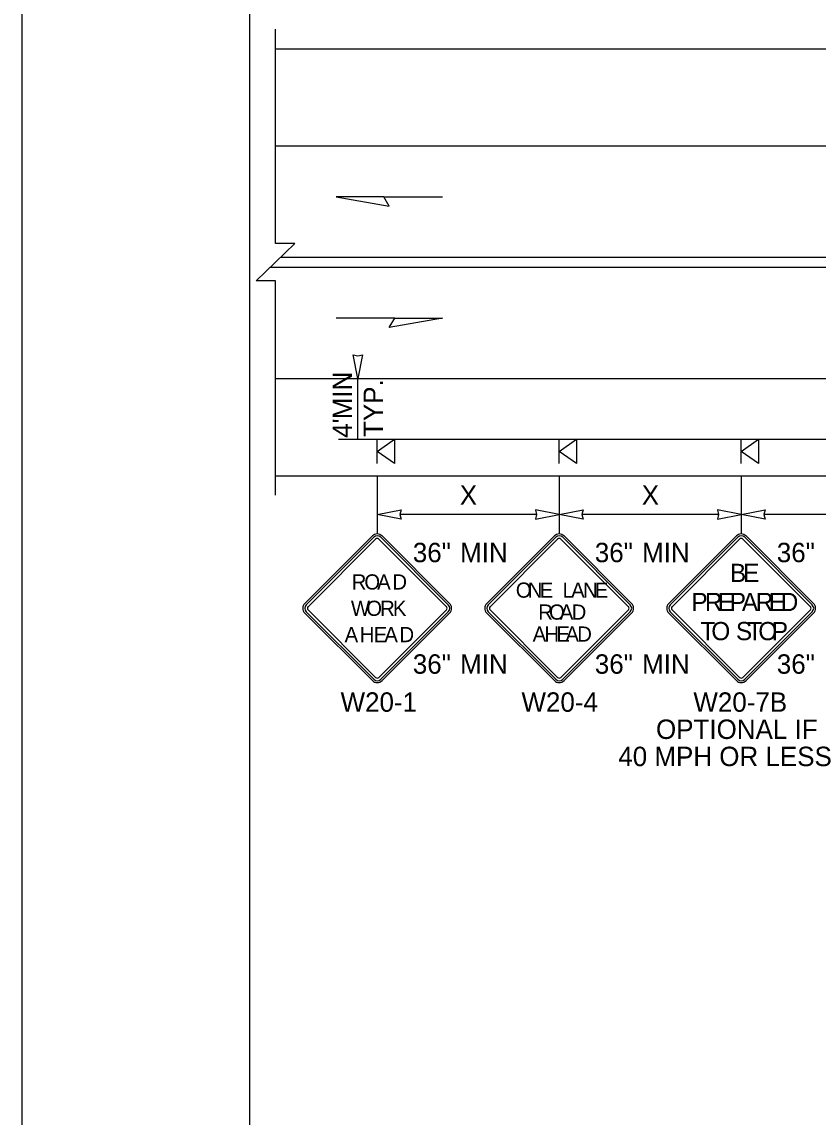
# Model space of a CAD drawing. Extents: x 99999.1 to 100095.7, y 99995 to 100010.7.
# Drawn here: x 99999.062 to 100002.344, y 100003.089 to 100007.603 of the extents above; entities that cross this region are included whole.
import ezdxf

# ---------------------------------------------------------------- set-up
doc = ezdxf.new("R2010")
doc.units = 0
for name, color, linetype in [('RD_ED_ShoulderPavedEdge', 7, 'Continuous'), ('RD_MK_LineDblYellowCenter', 7, 'Continuous'), ('RD_MK_LineEdgeWhite', 7, 'Continuous'), ('SH_GI_PlotLimits', 7, 'Continuous'), ('SH_GI_SheetBorder', 7, 'Continuous'), ('TR_SN_ConstructionSigns', 7, 'Continuous'), ('TR_WZ_PortableSignMountBlk-Org', 7, 'Continuous'), ('TR_WZ_WorkZoneDetails', 7, 'Continuous'), ('TR_WZ_WorkZoneTextCurrent', 7, 'Continuous')]:
    doc.layers.add(name, color=color, linetype=linetype)

msp = doc.modelspace()

# ---------------------------------------------------------------- linework, layer by layer
at = {"layer": 'RD_ED_ShoulderPavedEdge'}
for p, q in [((100000.1076, 100007.4923), (100015.6424, 100007.4923)), ((100000.1076, 100005.7323), (100015.6424, 100005.7323))]:
    msp.add_line(p, q, dxfattribs=at)
at = {"layer": 'RD_MK_LineDblYellowCenter'}
for p, q in [((100000.1282, 100006.6323), (100003.4767, 100006.6323)), ((100000.0869, 100006.5923), (100003.4767, 100006.5923))]:
    msp.add_line(p, q, dxfattribs=at)
at = {"layer": 'RD_MK_LineEdgeWhite'}
for p, q in [((100000.1076, 100007.0923), (100015.6424, 100007.0923)), ((100000.1076, 100006.1323), (100015.6424, 100006.1323))]:
    msp.add_line(p, q, dxfattribs=at)
at = {"layer": 'SH_GI_PlotLimits'}
msp.add_lwpolyline([(99999.0625, 99999.6875), (100016.0625, 99999.6875), (100016.0625, 100010.6875), (99999.0625, 100010.6875)], close=True, dxfattribs=at)
at = {"layer": 'SH_GI_SheetBorder'}
msp.add_line((100000, 100010.375), (100000, 100000), dxfattribs=at)
at = {"layer": 'TR_SN_ConstructionSigns'}
for p, q in [((100000.5068, 100005.4841), (100000.2283, 100005.2057)), ((100000.5123, 100005.4786), (100000.2339, 100005.2001)), ((100000.2416, 100005.1924), (100000.52, 100005.4708)), ((100000.5333, 100005.4708), (100000.8117, 100005.1924)), ((100000.8194, 100005.2001), (100000.541, 100005.4786)), ((100000.825, 100005.2057), (100000.5465, 100005.4841)), ((100001.2568, 100005.4841), (100000.9783, 100005.2057)), ((100001.2623, 100005.4786), (100000.9839, 100005.2001)), ((100000.9916, 100005.1924), (100001.27, 100005.4708)), ((100001.2833, 100005.4708), (100001.5617, 100005.1924)), ((100001.5694, 100005.2001), (100001.291, 100005.4786)), ((100001.575, 100005.2057), (100001.2965, 100005.4841)), ((100002.0068, 100005.4841), (100001.7283, 100005.2057)), ((100002.0123, 100005.4786), (100001.7339, 100005.2001)), ((100001.7416, 100005.1924), (100002.02, 100005.4708)), ((100002.0333, 100005.4708), (100002.3117, 100005.1924)), ((100002.3194, 100005.2001), (100002.041, 100005.4786)), ((100002.325, 100005.2057), (100002.0465, 100005.4841)), ((100000.52, 100004.9007), (100000.2416, 100005.1792)), ((100000.8117, 100005.1792), (100000.5333, 100004.9007)), ((100001.27, 100004.9007), (100000.9916, 100005.1792)), ((100001.5617, 100005.1792), (100001.2833, 100004.9007)), ((100002.02, 100004.9007), (100001.7416, 100005.1792)), ((100002.3117, 100005.1792), (100002.0333, 100004.9007)), ((100000.2283, 100005.1659), (100000.5068, 100004.8875)), ((100000.2339, 100005.1714), (100000.5123, 100004.893)), ((100000.541, 100004.893), (100000.8194, 100005.1714)), ((100000.5465, 100004.8875), (100000.825, 100005.1659)), ((100000.9783, 100005.1659), (100001.2568, 100004.8875)), ((100000.9839, 100005.1714), (100001.2623, 100004.893)), ((100001.291, 100004.893), (100001.5694, 100005.1714)), ((100001.2965, 100004.8875), (100001.575, 100005.1659)), ((100001.7283, 100005.1659), (100002.0068, 100004.8875)), ((100001.7339, 100005.1714), (100002.0123, 100004.893)), ((100002.041, 100004.893), (100002.3194, 100005.1714)), ((100002.0465, 100004.8875), (100002.325, 100005.1659))]:
    msp.add_line(p, q, dxfattribs=at)
for centre, radius, start, end in [((100000.5267, 100005.4642), 0.0281, 45, 135), ((100000.5267, 100005.4642), 0.0203, 45, 135), ((100000.5267, 100005.4642), 0.00937, 45, 135), ((100001.2767, 100005.4642), 0.0281, 45, 135), ((100001.2767, 100005.4642), 0.0203, 45, 135), ((100001.2767, 100005.4642), 0.00937, 45, 135), ((100002.0267, 100005.4642), 0.0281, 45, 135), ((100002.0267, 100005.4642), 0.0203, 45, 135), ((100002.0267, 100005.4642), 0.00937, 45, 135), ((100000.2482, 100005.1858), 0.0281, 135, 225), ((100000.2482, 100005.1858), 0.0203, 135, 225), ((100000.2482, 100005.1858), 0.00937, 135, 225), ((100000.8051, 100005.1858), 0.00937, 315, 45), ((100000.8051, 100005.1858), 0.0203, 315, 45), ((100000.8051, 100005.1858), 0.0281, 315, 45), ((100000.9982, 100005.1858), 0.0281, 135, 225), ((100000.9982, 100005.1858), 0.0203, 135, 225), ((100000.9982, 100005.1858), 0.00937, 135, 225), ((100001.5551, 100005.1858), 0.00937, 315, 45), ((100001.5551, 100005.1858), 0.0203, 315, 45), ((100001.5551, 100005.1858), 0.0281, 315, 45), ((100001.7482, 100005.1858), 0.0281, 135, 225), ((100001.7482, 100005.1858), 0.0203, 135, 225), ((100001.7482, 100005.1858), 0.00937, 135, 225), ((100002.3051, 100005.1858), 0.00937, 315, 45), ((100002.3051, 100005.1858), 0.0203, 315, 45), ((100002.3051, 100005.1858), 0.0281, 315, 45), ((100000.5267, 100004.9074), 0.0281, 225, 315), ((100000.5267, 100004.9074), 0.0203, 225, 315), ((100000.5267, 100004.9074), 0.00937, 225, 315), ((100001.2767, 100004.9074), 0.0281, 225, 315), ((100001.2767, 100004.9074), 0.0203, 225, 315), ((100001.2767, 100004.9074), 0.00937, 225, 315), ((100002.0267, 100004.9074), 0.0281, 225, 315), ((100002.0267, 100004.9074), 0.0203, 225, 315), ((100002.0267, 100004.9074), 0.00937, 225, 315)]:
    msp.add_arc(centre, radius, start, end, dxfattribs=at)
at = {"layer": 'TR_WZ_PortableSignMountBlk-Org'}
for p, q in [((100000.5267, 100005.7824), (100000.5267, 100005.8824)), ((100001.2767, 100005.7824), (100001.2767, 100005.8824)), ((100002.0267, 100005.7824), (100002.0267, 100005.8824))]:
    msp.add_line(p, q, dxfattribs=at)
for points in [[(100000.5267, 100005.8323), (100000.5985, 100005.8824), (100000.5985, 100005.7824)], [(100001.2767, 100005.8323), (100001.3485, 100005.8824), (100001.3485, 100005.7824)], [(100002.0267, 100005.8323), (100002.0985, 100005.8824), (100002.0985, 100005.7824)]]:
    msp.add_lwpolyline(points, close=True, dxfattribs=at)
at = {"layer": 'TR_WZ_WorkZoneDetails'}
for p, q in [((100000.5541, 100006.8816), (100000.7952, 100006.8816)), ((100000.5987, 100006.3816), (100000.3576, 100006.3816)), ((100000.3667, 100006.1323), (100000.5267, 100006.1323)), ((100000.4467, 100005.8824), (100000.4467, 100006.1323)), ((100000.3667, 100005.8824), (100000.5267, 100005.8824)), ((100000.5267, 100005.8824), (100003.5267, 100005.8824)), ((100000.5267, 100005.7326), (100000.5267, 100005.4923)), ((100001.2767, 100005.7323), (100001.2767, 100005.4923)), ((100002.0267, 100005.7323), (100002.0267, 100005.4923)), ((100001.1829, 100005.5723), (100000.6204, 100005.5723)), ((100001.9329, 100005.5723), (100001.3704, 100005.5723)), ((100002.6829, 100005.5723), (100002.1204, 100005.5723))]:
    msp.add_line(p, q, dxfattribs=at)
msp.add_lwpolyline([(100000.1076, 100005.6523), (100000.1076, 100006.5349), (100000.0275, 100006.5349), (100000.1876, 100006.6898), (100000.1076, 100006.6898), (100000.1076, 100007.5723)], dxfattribs=at)
for points in [[(100000.3576, 100006.8816), (100000.5764, 100006.843), (100000.5541, 100006.8816)], [(100000.7952, 100006.3816), (100000.5764, 100006.343), (100000.5987, 100006.3816)], [(100000.4467, 100006.1323), (100000.4274, 100006.2306), (100000.4467, 100006.2261), (100000.4659, 100006.2306)], [(100000.5267, 100005.5723), (100000.6249, 100005.5916), (100000.6204, 100005.5723), (100000.6249, 100005.5531)], [(100001.2767, 100005.5723), (100001.1784, 100005.5916), (100001.1829, 100005.5723), (100001.1784, 100005.5531)], [(100001.2767, 100005.5723), (100001.3749, 100005.5916), (100001.3704, 100005.5723), (100001.3749, 100005.5531)], [(100002.0267, 100005.5723), (100001.9284, 100005.5916), (100001.9329, 100005.5723), (100001.9284, 100005.5531)], [(100002.0267, 100005.5723), (100002.1249, 100005.5916), (100002.1204, 100005.5723), (100002.1249, 100005.5531)]]:
    msp.add_lwpolyline(points, close=True, dxfattribs=at)

# ---------------------------------------------------------------- texts
at = {"layer": 'TR_SN_ConstructionSigns'}
for s, p in [('36"', (100000.6734, 100005.3756)), ('MIN', (100000.8684, 100005.3756)), ('36"', (100001.4234, 100005.3756)), ('MIN', (100001.6184, 100005.3756)), ('36"', (100002.1734, 100005.3756)), ('36"', (100000.6734, 100004.916)), ('36"', (100001.4234, 100004.916)), ('36"', (100002.1734, 100004.916)), ('MIN', (100000.8684, 100004.916)), ('MIN', (100001.6184, 100004.916)), ('W20-1', (100000.3757, 100004.7592)), ('W20-4', (100001.1212, 100004.7592)), ('W20-7B', (100001.8296, 100004.7592)), ('OPTIONAL IF', (100001.6757, 100004.6472)), ('40 MPH OR LESS', (100001.5202, 100004.5352))]:
    msp.add_text(s, height=0.08, rotation=360, dxfattribs=at).set_placement(p)
for s, height, p in [('B', 0.075, (100001.9804, 100005.2943)), ('E', 0.075, (100002.0347, 100005.2943)), ('R', 0.0625, (100000.4216, 100005.2631)), ('O', 0.0625, (100000.4737, 100005.2631)), ('A', 0.0625, (100000.5265, 100005.2631)), ('D', 0.0625, (100000.5892, 100005.2631)), ('O', 0.0625, (100001.0979, 100005.2295)), ('N', 0.0625, (100001.1473, 100005.2295)), ('E', 0.0625, (100001.196, 100005.2295)), ('L', 0.0625, (100001.2904, 100005.2295)), ('A', 0.0625, (100001.326, 100005.2295)), ('N', 0.0625, (100001.3748, 100005.2295)), ('E', 0.0625, (100001.4235, 100005.2295)), ('P', 0.075, (100001.8218, 100005.1743)), ('R', 0.075, (100001.877, 100005.1743)), ('E', 0.075, (100001.9302, 100005.1743)), ('P', 0.075, (100001.9797, 100005.1743)), ('A', 0.075, (100002.0296, 100005.1743)), ('R', 0.075, (100002.0868, 100005.1743)), ('E', 0.075, (100002.1401, 100005.1743)), ('D', 0.075, (100002.1896, 100005.1743)), ('W', 0.0625, (100000.4183, 100005.1545)), ('O', 0.0625, (100000.4816, 100005.1545)), ('R', 0.0625, (100000.5388, 100005.1545)), ('K', 0.0625, (100000.5912, 100005.1545)), ('R', 0.0625, (100001.1904, 100005.1389)), ('O', 0.0625, (100001.2348, 100005.1389)), ('A', 0.0625, (100001.2792, 100005.1389)), ('D', 0.0625, (100001.3279, 100005.1389)), ('A', 0.0625, (100000.3923, 100005.046)), ('H', 0.0625, (100000.4548, 100005.046)), ('E', 0.0625, (100000.5123, 100005.046)), ('A', 0.0625, (100000.556, 100005.046)), ('D', 0.0625, (100000.6185, 100005.046)), ('A', 0.0625, (100001.1673, 100005.0483)), ('H', 0.0625, (100001.216, 100005.0483)), ('E', 0.0625, (100001.2648, 100005.0483)), ('A', 0.0625, (100001.3023, 100005.0483)), ('D', 0.0625, (100001.351, 100005.0483)), ('T', 0.075, (100001.8584, 100005.0543)), ('O', 0.075, (100001.9035, 100005.0543)), ('S', 0.075, (100002.005, 100005.0543)), ('T', 0.075, (100002.0521, 100005.0543)), ('O', 0.075, (100002.0972, 100005.0543)), ('P', 0.075, (100002.1529, 100005.0543))]:
    msp.add_text(s, height=height, dxfattribs=at).set_placement(p)
at = {"layer": 'TR_WZ_WorkZoneTextCurrent'}
for s, rotation, p in [('MIN', 90, (100000.4227, 100005.9648)), ('TYP.', 90, (100000.5507, 100005.892)), ("4'", 90, (100000.4227, 100005.8883)), ('X', 360, (100000.8669, 100005.6123)), ('X', 360, (100001.6169, 100005.6123))]:
    msp.add_text(s, height=0.08, rotation=rotation, dxfattribs=at).set_placement(p)

doc.saveas('drawing.dxf')
